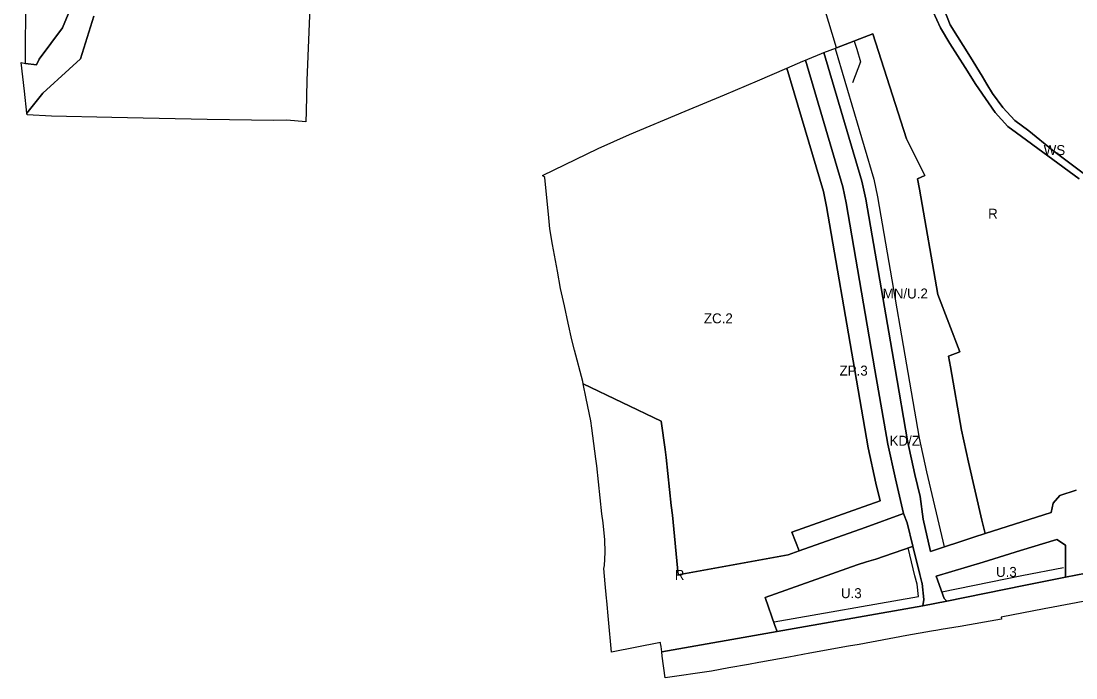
# Model space of a CAD drawing. Extents: x 7438199 to 7440548, y 5549253 to 5551017.
# Drawn here: x 7438541 to 7439598, y 5549253 to 5549912 of the extents above; entities that cross this region are included whole.
import ezdxf

# ---------------------------------------------------------------- set-up
doc = ezdxf.new("R2010")
doc.units = 0
for name, color, linetype in [('linie_rozgraniczajace', 7, 'Continuous'), ('linie_zabudowy_nieprzekraczalne', 7, 'Continuous'), ('oznaczenia_przeznaczen', 7, 'Continuous')]:
    doc.layers.add(name, color=color, linetype=linetype)

msp = doc.modelspace()

# ---------------------------------------------------------------- linework, layer by layer
at = {"layer": 'linie_rozgraniczajace'}
for points in [[(7439606.18, 5549758.61), (7439574.15, 5549782.83), (7439550.33, 5549802), (7439536.49, 5549812.69), (7439524.42, 5549825.6), (7439514.03, 5549839.75), (7439508.38, 5549849.1), (7439503.53, 5549857.03), (7439491.93, 5549876), (7439471.74, 5549908.46), (7439460.34, 5549937.99), (7439453.06, 5549969.08), (7439443.91, 5550026.51), (7439443.9, 5550026.58), (7439436.61, 5550079.32), (7439435.31, 5550085.77), (7439434.01, 5550092.19), (7439445.25, 5550090.39), (7439462.38, 5550088.37), (7439479.57, 5550087.06), (7439496.81, 5550086.46), (7439514.05, 5550086.59), (7439670.68, 5550104.35)], [(7438613.31, 5549917.27), (7438600.02, 5549874.4), (7438588.8, 5549864.18), (7438562.16, 5549839.93), (7438546.32, 5549820.02), (7438543.96, 5549841.94), (7438540.51, 5549870.65), (7438545.03, 5549869.81), (7438555.89, 5549868.27), (7438558.46, 5549874.09), (7438581.96, 5549905.55), (7438597.73, 5549943.7)], [(7438597.73, 5549943.7), (7438581.96, 5549905.55), (7438558.46, 5549874.09), (7438555.89, 5549868.27), (7438545.03, 5549869.81), (7438545.17, 5549938.29)], [(7439460.34, 5549937.99), (7439471.74, 5549908.46), (7439491.93, 5549876), (7439503.53, 5549857.03), (7439508.38, 5549849.1), (7439514.03, 5549839.75), (7439524.42, 5549825.6), (7439536.49, 5549812.69), (7439550.33, 5549802), (7439574.15, 5549782.83), (7439606.18, 5549758.61)], [(7438830.01, 5549925.79), (7438827.02, 5549852.66), (7438826.13, 5549821.42), (7438825.84, 5549811.09), (7438806.89, 5549812.93), (7438793.65, 5549812.56), (7438726.99, 5549813.39), (7438662.74, 5549814.79), (7438631.48, 5549815.54), (7438571.06, 5549816.99), (7438546.54, 5549818.05), (7438546.32, 5549820.02), (7438562.16, 5549839.93), (7438588.8, 5549864.18), (7438600.02, 5549874.4), (7438613.31, 5549917.27)], [(7439597.9, 5549441.69), (7439581.68, 5549436.46), (7439574.95, 5549428.87), (7439572.8, 5549419.3), (7439506.65, 5549398.14), (7439503.5, 5549411.57), (7439489.9, 5549469.71), (7439482.87, 5549501.88), (7439471.86, 5549565.55), (7439470.02, 5549576.14), (7439481.25, 5549580.41), (7439459.3, 5549638.1), (7439441.04, 5549743.69), (7439438.93, 5549753.93), (7439446.17, 5549757.28), (7439427.8, 5549794.25), (7439394.28, 5549899.39), (7439357.84, 5549885.47), (7439345.79, 5549925.11)], [(7439601.05, 5549753.98), (7439538.2, 5549800.16), (7439529.52, 5549806.54), (7439516.65, 5549820.65), (7439509.98, 5549830.27), (7439497.25, 5549848.65), (7439486.68, 5549865.55), (7439471.34, 5549889.74), (7439461.84, 5549905.59), (7439454.65, 5549921.6)], [(7439454.65, 5549921.6), (7439461.84, 5549905.59), (7439471.34, 5549889.74), (7439486.68, 5549865.55), (7439497.25, 5549848.65), (7439509.98, 5549830.27), (7439516.65, 5549820.65), (7439529.52, 5549806.54), (7439538.2, 5549800.16), (7439601.05, 5549753.98)], [(7439607.96, 5549358.49), (7439587.2, 5549354.42), (7439587.32, 5549386.7), (7439578.37, 5549392.19), (7439542, 5549381.14), (7439504.74, 5549369.53), (7439457.56, 5549355.56), (7439465.5, 5549333.19), (7439468.33, 5549330.52), (7439444.13, 5549325.59), (7439445.35, 5549332.06), (7439443.45, 5549348.2), (7439443.24, 5549349.09), (7439441.22, 5549357.18), (7439434.32, 5549385.49), (7439434.17, 5549385.44), (7439434.17, 5549385.45), (7439428.53, 5549409.14), (7439424.94, 5549418.18), (7439416.78, 5549453.02), (7439409.18, 5549487.91), (7439396.28, 5549562.48), (7439367.29, 5549730.05), (7439364.07, 5549746), (7439326.49, 5549872.99), (7439328.99, 5549874.07), (7439342.69, 5549879.71), (7439345.09, 5549880.62), (7439383.25, 5549751.67), (7439386.99, 5549733.46), (7439416.43, 5549563.3), (7439428.89, 5549491.32), (7439436.26, 5549457.58), (7439441.47, 5549435.29), (7439444.46, 5549412.5), (7439451.78, 5549380.23), (7439495.31, 5549394.51), (7439506.65, 5549398.14), (7439572.8, 5549419.3), (7439574.95, 5549428.87), (7439581.68, 5549436.46), (7439597.9, 5549441.69)], [(7439182.54, 5549279.71), (7439298.13, 5549299.99), (7439444.13, 5549325.59), (7439468.33, 5549330.52), (7439545.44, 5549346.23), (7439587.2, 5549354.42), (7439607.96, 5549358.49)], [(7439622.73, 5549333.39), (7439574.7, 5549324.39), (7439565.91, 5549322.75), (7439522.87, 5549314.25)], [(7439522.87, 5549314.25), (7439523.12, 5549312.24), (7439506.07, 5549309.32), (7439481.53, 5549305.11), (7439462.76, 5549301.86), (7439459.41, 5549301.28), (7439452.99, 5549300.17), (7439428.34, 5549295.9), (7439380.33, 5549287.1), (7439369.62, 5549285.17), (7439331.12, 5549278.23), (7439309.93, 5549274.34), (7439281.71, 5549269.16), (7439279.98, 5549268.85), (7439269.35, 5549266.95), (7439249.7, 5549263.43), (7439232.54, 5549260.35), (7439186.07, 5549253.42), (7439183.14, 5549275.27), (7439182.54, 5549279.71)]]:
    msp.add_lwpolyline(points, dxfattribs=at)
for points in [[(7439345.09, 5549880.62), (7439357.84, 5549885.47), (7439394.28, 5549899.39), (7439427.8, 5549794.25), (7439446.17, 5549757.28), (7439438.93, 5549753.93), (7439441.04, 5549743.69), (7439459.3, 5549638.1), (7439481.25, 5549580.41), (7439470.02, 5549576.14), (7439471.86, 5549565.55), (7439482.87, 5549501.88), (7439489.9, 5549469.71), (7439503.5, 5549411.57), (7439506.65, 5549398.14), (7439495.31, 5549394.51), (7439451.78, 5549380.23), (7439444.46, 5549412.5), (7439441.47, 5549435.29), (7439436.26, 5549457.58), (7439428.89, 5549491.32), (7439416.43, 5549563.3), (7439386.99, 5549733.46), (7439383.25, 5549751.67)], [(7439312.96, 5549399.55), (7439379.65, 5549423.21), (7439401.4, 5549431), (7439397.28, 5549448.62), (7439389.55, 5549484.08), (7439376.12, 5549561.67), (7439347.63, 5549726.37), (7439344.64, 5549741.18), (7439307.99, 5549865.02), (7439323.94, 5549871.89), (7439326.49, 5549872.99), (7439364.07, 5549746), (7439367.29, 5549730.05), (7439396.28, 5549562.48), (7439409.18, 5549487.91), (7439416.78, 5549453.02), (7439424.94, 5549418.18), (7439386.36, 5549404.38), (7439320.27, 5549380.92)], [(7439063.16, 5549757.38), (7439118.75, 5549784.29), (7439150.35, 5549798.36), (7439206.16, 5549822.04), (7439245.31, 5549838.43), (7439278.38, 5549852.27), (7439307.99, 5549865.02), (7439344.64, 5549741.18), (7439347.63, 5549726.37), (7439376.12, 5549561.67), (7439389.55, 5549484.08), (7439397.28, 5549448.62), (7439401.4, 5549431), (7439379.65, 5549423.21), (7439312.96, 5549399.55), (7439320.27, 5549380.92), (7439309.34, 5549377.04), (7439198.87, 5549356.72), (7439193.36, 5549416.73), (7439192.07, 5549426.36), (7439187.07, 5549474.61), (7439185.95, 5549482.68), (7439182.04, 5549510.89), (7439103.88, 5549548.27), (7439103.41, 5549550.6), (7439103.4, 5549550.65), (7439095.12, 5549582.15), (7439092.39, 5549592.53), (7439088.75, 5549609.19), (7439084.95, 5549626.61), (7439081.17, 5549643.95), (7439078.01, 5549661.43), (7439073.2, 5549688), (7439070.33, 5549703.87), (7439069.27, 5549714.75), (7439065.38, 5549755.25)], [(7439103.88, 5549548.27), (7439182.04, 5549510.89), (7439185.95, 5549482.68), (7439187.07, 5549474.61), (7439192.07, 5549426.36), (7439193.36, 5549416.73), (7439198.87, 5549356.72), (7439309.34, 5549377.04), (7439320.27, 5549380.92), (7439386.36, 5549404.38), (7439424.94, 5549418.18), (7439428.53, 5549409.14), (7439434.17, 5549385.45), (7439432.71, 5549384.96), (7439397.06, 5549372.64), (7439387.82, 5549369.8), (7439378.26, 5549366.81), (7439286.37, 5549334.19), (7439296.04, 5549306.13), (7439298.13, 5549299.99), (7439182.54, 5549279.71), (7439181.83, 5549285.06), (7439181.43, 5549287.99), (7439181.32, 5549288.86), (7439132.15, 5549279.27), (7439129.18, 5549311.96), (7439127.48, 5549330.64), (7439127.25, 5549333.27), (7439125.91, 5549347.92), (7439124.52, 5549363.27), (7439125.15, 5549366.28), (7439125.83, 5549379.29), (7439125.43, 5549392.18), (7439124.43, 5549401.86), (7439123.79, 5549408.88), (7439122.55, 5549418.11), (7439117.57, 5549466.21), (7439116.62, 5549473.09), (7439112.35, 5549503.9), (7439111.34, 5549511.16), (7439106.85, 5549533.52)], [(7439286.37, 5549334.19), (7439378.26, 5549366.81), (7439387.82, 5549369.8), (7439397.06, 5549372.64), (7439432.71, 5549384.96), (7439434.17, 5549385.45), (7439434.17, 5549385.44), (7439434.32, 5549385.49), (7439441.22, 5549357.18), (7439443.24, 5549349.09), (7439443.45, 5549348.2), (7439445.35, 5549332.06), (7439444.13, 5549325.59), (7439298.13, 5549299.99), (7439296.04, 5549306.13)], [(7439457.56, 5549355.56), (7439504.74, 5549369.53), (7439542, 5549381.14), (7439578.37, 5549392.19), (7439587.32, 5549386.7), (7439587.2, 5549354.42), (7439545.44, 5549346.23), (7439468.33, 5549330.52), (7439465.5, 5549333.19)]]:
    msp.add_lwpolyline(points, close=True, dxfattribs=at)
at = {"layer": 'linie_zabudowy_nieprzekraczalne'}
for points in [[(7439375.55, 5549892.2), (7439377.95, 5549884.06), (7439381.72, 5549871.27), (7439373.75, 5549850.16)], [(7439356.38, 5549884.75), (7439395.16, 5549753.71), (7439398.74, 5549735.94), (7439440.59, 5549494.05), (7439448, 5549460.07), (7439465.62, 5549384.77)], [(7439295.09, 5549309.6), (7439439.97, 5549335.01), (7439438.51, 5549347.38), (7439436.37, 5549355.98), (7439429.56, 5549383.87)], [(7439463.2, 5549339.68), (7439543.48, 5549356.03), (7439585.27, 5549364.23)]]:
    msp.add_lwpolyline(points, dxfattribs=at)

# ---------------------------------------------------------------- texts
at = {"layer": 'oznaczenia_przeznaczen'}
for s, p in [('WS', (7439565.37, 5549777.83)), ('R', (7439509.67, 5549714.05)), ('MN/U.2', (7439403.95, 5549634)), ('ZC.2', (7439224.82, 5549609.07)), ('ZP.3', (7439360.77, 5549556.67)), ('KD/Z', (7439410.86, 5549486.32)), ('R', (7439195.6, 5549351.72)), ('U.3', (7439517.54, 5549354.75)), ('U.3', (7439362.14, 5549333.43))]:
    msp.add_text(s, height=10, dxfattribs=at).set_placement(p)

doc.saveas('drawing.dxf')
